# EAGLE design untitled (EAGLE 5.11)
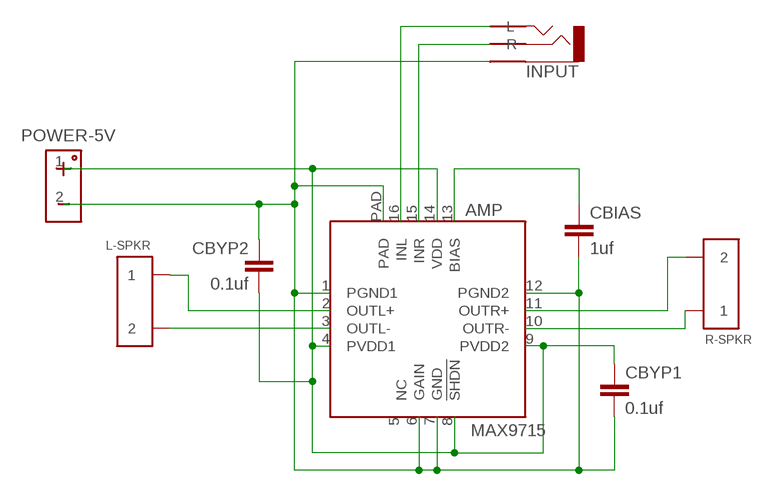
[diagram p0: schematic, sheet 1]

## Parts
AMP  MAX9715  [QFN16-5X5-0.8PITCH-PAD]
CBIAS  1uf  C-EUC0805  [C0805]
CBYP1  0.1uf  C-EUC0805  [C0805]
CBYP2  0.1uf  C-EUC0805  [C0805]
INPUT  AUDIO-JACK-STEREO-3PIN948  [AUDIO-JACK-STEREO-3PIN-948]
L-SPKR  SCREW-CLAMP-2908  [SCREW-CLAMP-PUSHIN-2-2.5MM]
POWER-5V  HEADER-POWERSMD  [HEADER-POWER-SMD]
R-SPKR  SCREW-CLAMP-2908  [SCREW-CLAMP-PUSHIN-2-2.5MM]

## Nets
GND: AMP.1(PGND1) AMP.6(GAIN) AMP.7(GND) AMP.12(PGND2) AMP.PAD CBIAS.2 CBYP1.2 CBYP2.1 INPUT.1(COM) POWER-5V.2
N$1: AMP.2(OUTL+) L-SPKR.1
N$2: AMP.13(BIAS) CBIAS.1
N$3: AMP.3(OUTL-) L-SPKR.2
N$4: AMP.10(OUTR-) R-SPKR.1
N$5: AMP.11(OUTR+) R-SPKR.2
N$6: AMP.15(INR) INPUT.3(R)
N$7: AMP.16(INL) INPUT.2(L)
VDD: AMP.4(PVDD1) AMP.8(!SHDN) AMP.9(PVDD2) AMP.14(VDD) CBYP1.1 CBYP2.2 POWER-5V.1
Unconnected: AMP.5(NC)

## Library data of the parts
AMP = trl:MAX9715
CBIAS CBYP1 CBYP2 = rcl:C-EU: CAPACITOR, European symbol
INPUT = trl:AUDIO-JACK-STEREO-3PIN
L-SPKR R-SPKR = trl:SCREW-CLAMP-2
POWER-5V = trl:HEADER-POWER

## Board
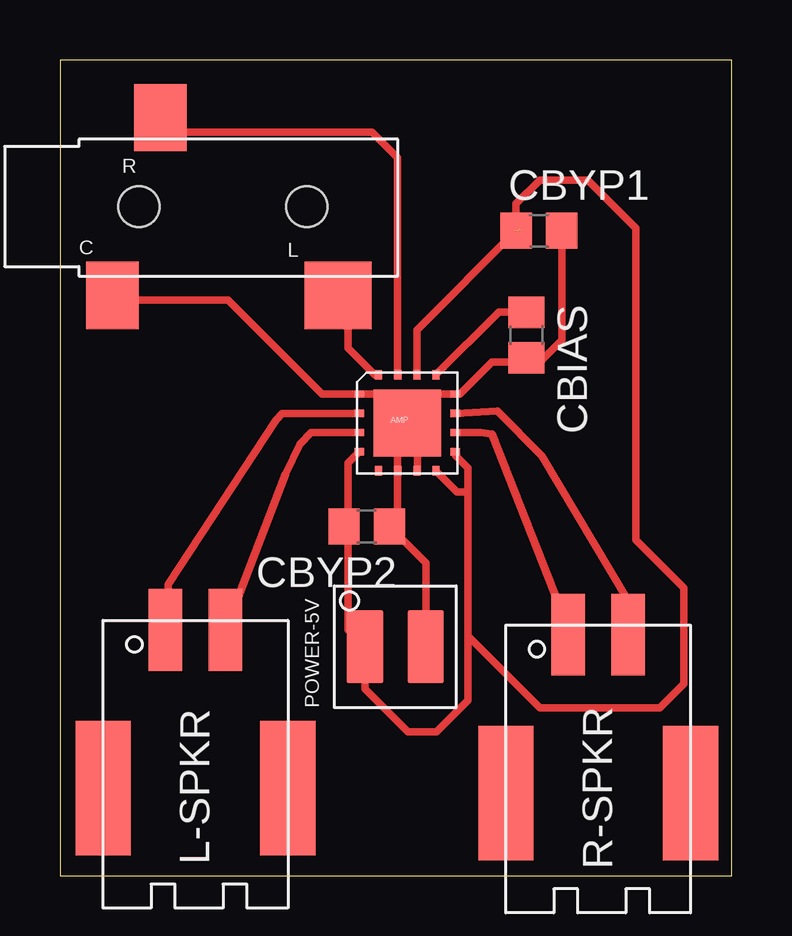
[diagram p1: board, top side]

Size 28 x 34 mm. Coordinates in mm from the lower left corner, seen from the top.
Outline: 0,0 28,0 28,34 0,34 0,0
Copper layers (1*16): Top 0.035mm / dielectric 1.5mm / Bottom 0.035mm
Design rules "default": minimum track width 10mil, minimum drill 0.6mm, track to track 8mil, track to pad 8mil, pad to pad 8mil, via to via 8mil, smd to smd 8mil, copper to edge 40mil, drill to drill 8mil, minimum pad ring 10mil, minimum via ring 8mil, stop-mask expansion 4mil, vias tented up to drill 0mil, thermal gap 10mil

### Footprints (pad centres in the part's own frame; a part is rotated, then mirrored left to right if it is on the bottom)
QFN16-5X5-0.8PITCH-PAD = smd 0.4 x 0.3: 1 0,0; 2 0,-0.8; 3 0,-1.6; 4 0,-2.4; 9 4,-2.4; 10 4,-1.6; 11 4,-0.8; 12 4,0 | smd 0.3 x 0.4: 5 0.8,-3.2; 6 1.6,-3.2; 7 2.4,-3.2; 8 3.2,-3.2; 13 3.2,0.8; 14 2.4,0.8; 15 1.6,0.8; 16 0.8,0.8 | smd 2.8 x 2.8: PAD 2,-1.2
C0805 = smd 1.3 x 1.5: 1 -0.95,0; 2 0.95,0
AUDIO-JACK-STEREO-3PIN-948 = smd 2.2 x 2.8: 1 -3.81,-3.81; 3 -1.81,3.59 | smd 2.8 x 2.8: 2 5.59,-3.81 | hole 1.7: -2.71,-0.11; 4.29,-0.11
SCREW-CLAMP-PUSHIN-2-2.5MM = smd 1.4 x 3.4: 1 -1.21,5.33; 2 1.29,5.33 | smd 2.3 x 5.6: 11 -3.81,-1.27; 22 3.89,-1.27
HEADER-POWER-SMD = smd 3.048 x 1.524: 1 0,1.27; 2 0,-1.27

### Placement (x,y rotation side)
AMP  12.48,20.07 0 top
CBIAS  19.45,22.53 270 top
CBYP1  19.97,26.88 0 top
CBYP2  12.79,14.55 180 top
INPUT  6,28 0 top
L-SPKR  5.61,4.91 0 top
POWER-5V  13.98,9.54 90 top
R-SPKR  22.4,4.71 0 top

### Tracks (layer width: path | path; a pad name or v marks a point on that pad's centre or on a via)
GND
  Top 0.305: AMP.PAD 14.48,18.62 14.9,18.2 14.9,16.89 AMP.7 | AMP.PAD 15.2,19.59 15.2,19.8 15.47,20.07 AMP.12 16.67,20.07 18,21.4 19.27,21.4 CBIAS.2 19.73,21.3 19.9,21.3 20.92,22.32 CBYP1.2 | AMP.PAD 13.28,20.07 AMP.1 10.93,20.07 7,24 2.38,24 INPUT.1 | AMP.PAD 14.08,18.47 AMP.6 14.08,14.89 CBYP2.1 15.25,13.04 POWER-5V.2
N$1
  Top 0.305: AMP.2 9.27,19.27 9,19 4.5,12.14 L-SPKR.1
N$2
  Top 0.305: AMP.13 18.3,23.5 19.43,23.5 CBIAS.1
N$3
  Top 0.305: AMP.3 10.47,18.47 10,18 9.4,16.74 L-SPKR.2
N$4
  Top 0.305: AMP.10 17.53,18.47 18,18.4 21.3,10.03 R-SPKR.1
N$5
  Top 0.305: AMP.11 18.23,19.37 20.1,17.5 23.7,11.45 R-SPKR.2
N$6
  Top 0.305: AMP.15 14.08,29.92 13,31 4.78,31 INPUT.3
N$7
  Top 0.305: AMP.16 13.13,20.87 12,22 12,23.78 INPUT.2
VDD  (1 unrouted)
  Top 0.305: AMP.9 16.48,17.52 17,17 17,16 | 17,16 16.55,16 AMP.8 | 12,14.71 CBYP2.2 | 19.2,26.94 19.2,26.4 | 17,10 17,7.3 15.7,6 14.5,6 12.71,7.79 POWER-5V.1 12,10.25 12,14.71 | 17,10 17,16 | 12,14.71 12,17.19 AMP.4 | 17,10 20,7 25,7 26,8 26,12 24,14 24,27 22,29 20,29 19.02,28.02 CBYP1.1 14.88,22.74 AMP.14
